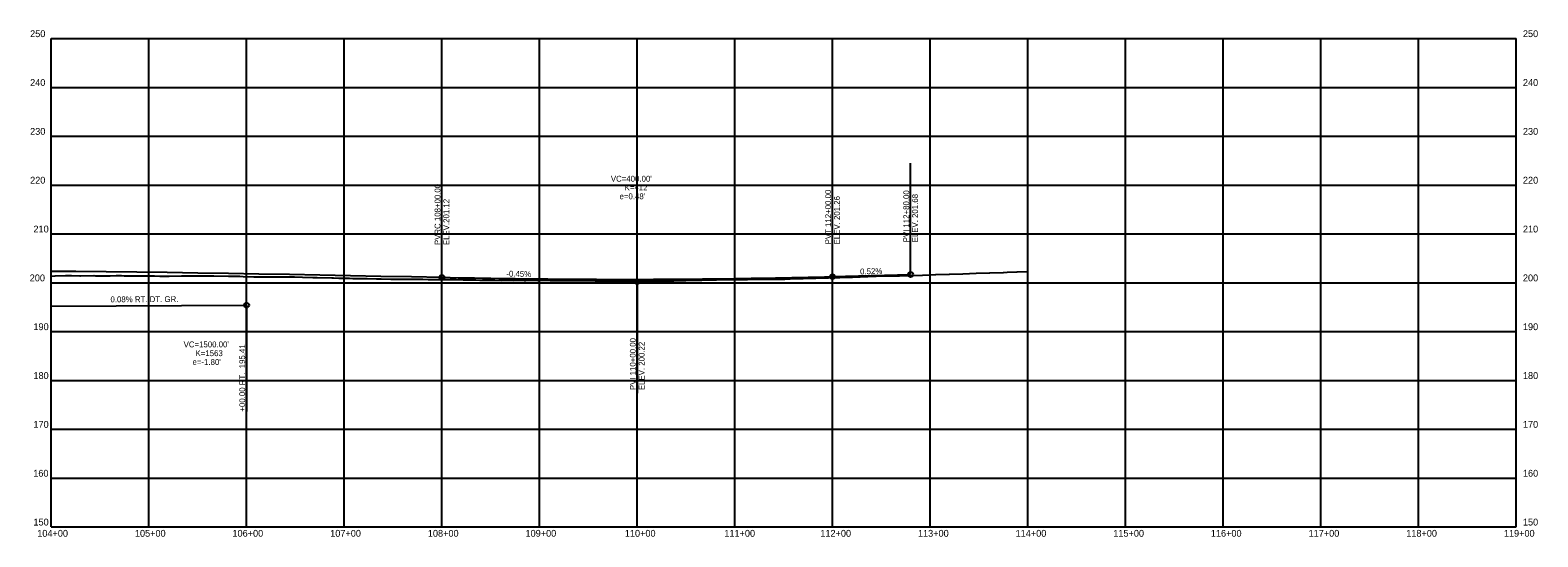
# Model space of a CAD drawing. Extents: x 1138442 to 1165793, y 1654070 to 1657687.
# Drawn here: x 1141789 to 1143333, y 1655756 to 1656275 of the extents above; entities that cross this region are included whole.
import ezdxf

# ---------------------------------------------------------------- set-up
doc = ezdxf.new("R2010")
doc.units = 0
for name, color, linetype in [('B_Dimensions', 7, 'Continuous'), ('R_Axis', 7, 'Continuous'), ('R_Axis Annot', 7, 'Continuous'), ('R_Grid', 7, 'Continuous'), ('R_Horz Alg Annot', 7, 'Continuous'), ('R_Proposed Const Limits_Hand', 7, 'Continuous'), ('R_Vert Alg Annot', 7, 'Continuous')]:
    doc.layers.add(name, color=color, linetype=linetype)

msp = doc.modelspace()

# ---------------------------------------------------------------- linework, layer by layer
at = {"layer": 'B_Dimensions'}
for p, q in [((1142610.9, 1656022.7), (1142690.9, 1656024.8)), ((1142310.9, 1656019.8), (1142410.9, 1656017.5)), ((1142410.9, 1656017.5), (1142510.9, 1656020.1)), ((1141810.9, 1655992.6), (1142010.9, 1655993.5))]:
    msp.add_line(p, q, dxfattribs=at)
for points in [[(1141810.9, 1656028.4), (1141835.9, 1656028.2), (1141867.2, 1656027.8), (1141898.4, 1656027.5), (1141929.7, 1656027.1), (1141960.9, 1656026.6), (1141992.2, 1656026.2), (1142023.4, 1656025.7), (1142054.7, 1656025.1), (1142085.9, 1656024.6), (1142117.2, 1656024), (1142148.4, 1656023.3), (1142179.7, 1656022.7), (1142210.9, 1656022)], [(1142210.9, 1656022), (1142219.3, 1656021.8), (1142227.6, 1656021.6), (1142235.9, 1656021.5), (1142244.3, 1656021.3), (1142252.6, 1656021.2), (1142260.9, 1656021), (1142269.3, 1656020.9), (1142277.6, 1656020.8), (1142285.9, 1656020.7), (1142294.3, 1656020.6), (1142302.6, 1656020.5), (1142310.9, 1656020.4), (1142319.3, 1656020.3), (1142327.6, 1656020.2), (1142335.9, 1656020.1), (1142344.3, 1656020.1), (1142352.6, 1656020), (1142360.9, 1656020), (1142369.3, 1656020), (1142377.6, 1656019.9), (1142385.9, 1656019.9), (1142394.3, 1656019.9), (1142402.6, 1656019.9), (1142419.3, 1656019.9), (1142427.6, 1656020), (1142435.9, 1656020), (1142444.3, 1656020.1), (1142452.6, 1656020.1), (1142460.9, 1656020.2), (1142469.3, 1656020.2), (1142477.6, 1656020.3), (1142485.9, 1656020.4), (1142494.3, 1656020.5), (1142502.6, 1656020.6), (1142510.9, 1656020.7), (1142519.3, 1656020.8), (1142527.6, 1656021), (1142535.9, 1656021.1), (1142544.3, 1656021.2), (1142552.6, 1656021.4), (1142560.9, 1656021.6), (1142569.3, 1656021.7), (1142577.6, 1656021.9), (1142585.9, 1656022.1), (1142594.3, 1656022.3), (1142602.6, 1656022.5), (1142610.9, 1656022.7)]]:
    msp.add_lwpolyline(points, dxfattribs=at)
msp.add_circle((1142010.9, 1655993.5), 2.5, dxfattribs=at)
at = {"layer": 'R_Axis'}
for p, q in [((1141810.9, 1655766.4), (1141810.9, 1656266.4)), ((1143310.9, 1655766.4), (1143310.9, 1656266.4)), ((1141810.9, 1655766.4), (1143310.9, 1655766.4))]:
    msp.add_line(p, q, dxfattribs=at)
at = {"layer": 'R_Grid'}
for p, q in [((1141810.9, 1656266.4), (1143310.9, 1656266.4)), ((1141810.9, 1656266.4), (1143310.9, 1656266.4)), ((1141910.9, 1655766.4), (1141910.9, 1656266.4)), ((1142010.9, 1655766.4), (1142010.9, 1656266.4)), ((1142110.9, 1655766.4), (1142110.9, 1656266.4)), ((1142210.9, 1655766.4), (1142210.9, 1656266.4)), ((1142310.9, 1655766.4), (1142310.9, 1656266.4)), ((1142410.9, 1655766.4), (1142410.9, 1656266.4)), ((1142510.9, 1655766.4), (1142510.9, 1656266.4)), ((1142610.9, 1655766.4), (1142610.9, 1656266.4)), ((1142710.9, 1655766.4), (1142710.9, 1656266.4)), ((1142810.9, 1655766.4), (1142810.9, 1656266.4)), ((1142910.9, 1655766.4), (1142910.9, 1656266.4)), ((1143010.9, 1655766.4), (1143010.9, 1656266.4)), ((1143110.9, 1655766.4), (1143110.9, 1656266.4)), ((1143210.9, 1655766.4), (1143210.9, 1656266.4)), ((1141810.9, 1656216.4), (1143310.9, 1656216.4)), ((1141810.9, 1656166.4), (1143310.9, 1656166.4)), ((1141810.9, 1656116.4), (1143310.9, 1656116.4)), ((1141810.9, 1656066.4), (1143310.9, 1656066.4)), ((1141810.9, 1656016.4), (1143310.9, 1656016.4)), ((1141810.9, 1655966.4), (1143310.9, 1655966.4)), ((1141810.9, 1655916.4), (1143310.9, 1655916.4)), ((1141810.9, 1655866.4), (1143310.9, 1655866.4)), ((1141810.9, 1655816.4), (1143310.9, 1655816.4))]:
    msp.add_line(p, q, dxfattribs=at)
at = {"layer": 'R_Proposed Const Limits_Hand'}
msp.add_lwpolyline([(1141810.9, 1656023.1), (1141814.7, 1656023.6), (1141825.3, 1656023.9), (1141825.7, 1656023.9), (1141831.5, 1656023.7), (1141840, 1656023.6), (1141840.8, 1656023.6), (1141854.4, 1656023.7), (1141856, 1656023.6), (1141861.7, 1656023.6), (1141871.1, 1656023.6), (1141877.4, 1656023.7), (1141882.7, 1656023.8), (1141885.6, 1656023.6), (1141886.3, 1656023.6), (1141899.6, 1656023.4), (1141901.4, 1656023.4), (1141906.2, 1656023.5), (1141916.6, 1656023.4), (1141922.2, 1656023.3), (1141925.6, 1656023.3), (1141931.7, 1656023.3), (1141944.1, 1656023.4), (1141946.9, 1656023.4), (1141947, 1656023.4), (1141949.6, 1656023.4), (1141962, 1656023.5), (1141969.4, 1656023.6), (1141971.3, 1656023.6), (1141977.2, 1656023.5), (1141992.3, 1656023.2), (1141994.1, 1656023.2), (1141994.9, 1656023.2), (1141995.6, 1656023.1), (1142003.8, 1656023), (1142007.5, 1656022.9), (1142018.2, 1656022.5), (1142019.2, 1656022.5), (1142022.6, 1656022.5), (1142037.7, 1656022.5), (1142038.1, 1656022.5), (1142039.5, 1656022.5), (1142052.9, 1656022.4), (1142057.8, 1656022.4), (1142059.9, 1656022.4), (1142068, 1656022.2), (1142078.6, 1656021.9), (1142082.4, 1656021.8), (1142083.2, 1656021.8), (1142098.3, 1656021.4), (1142100, 1656021.4), (1142105.2, 1656021.2), (1142113.5, 1656021.1), (1142116.4, 1656021), (1142119.7, 1656020.9), (1142128.6, 1656020.8), (1142130.6, 1656020.7), (1142134.2, 1656020.7), (1142143.8, 1656020.5), (1142144.6, 1656020.5), (1142148.6, 1656020.4), (1142158.5, 1656020.2), (1142158.9, 1656020.2), (1142163, 1656020.1), (1142172.2, 1656020.1), (1142174.1, 1656020.1), (1142177.2, 1656020), (1142186.2, 1656020), (1142189.2, 1656020), (1142191.4, 1656020), (1142196.9, 1656019.9), (1142204.4, 1656019.9), (1142205.6, 1656019.9), (1142211.4, 1656019.8), (1142219.5, 1656019.8), (1142219.8, 1656019.8), (1142225.5, 1656019.7), (1142232.7, 1656019.5), (1142234.7, 1656019.5), (1142238.7, 1656019.4), (1142245.7, 1656019.3), (1142249.8, 1656019.2), (1142251.9, 1656019.2), (1142258.7, 1656019.1), (1142265, 1656019), (1142265.2, 1656019), (1142271.6, 1656018.8), (1142278.2, 1656018.9), (1142280.1, 1656018.9), (1142284.2, 1656018.8), (1142291.1, 1656018.9), (1142295.2, 1656018.8), (1142296.7, 1656018.8), (1142304.1, 1656018.9), (1142309.2, 1656018.8), (1142310.4, 1656018.8), (1142317, 1656018.9), (1142321.8, 1656018.8), (1142325.5, 1656018.8), (1142326.4, 1656018.8), (1142334.8, 1656018.8), (1142339.2, 1656018.8), (1142340.7, 1656018.8), (1142347.8, 1656018.7), (1142351.9, 1656018.7), (1142355.8, 1656018.7), (1142360.8, 1656018.6), (1142364.6, 1656018.6), (1142371, 1656018.6), (1142373.8, 1656018.5), (1142380.2, 1656018.6), (1142386.1, 1656018.6), (1142397.5, 1656018.7), (1142401.3, 1656018.7), (1142402.9, 1656018.7), (1142416.4, 1656018.9), (1142421.1, 1656018.9), (1142423.7, 1656018.9), (1142431.6, 1656019), (1142435, 1656019), (1142446.7, 1656019), (1142446.7, 1656019), (1142448.9, 1656019), (1142460.9, 1656019.1), (1142461.9, 1656019.1), (1142462.8, 1656019.1), (1142475.1, 1656019.2), (1142476.7, 1656019.2), (1142477, 1656019.2), (1142490.9, 1656019.4), (1142492.2, 1656019.4), (1142506.9, 1656019.6), (1142507.8, 1656019.7), (1142522.9, 1656019.9), (1142523.4, 1656019.9), (1142523.8, 1656019.9), (1142538.9, 1656020.1), (1142538.9, 1656020.1), (1142539.1, 1656020.1), (1142554.7, 1656020), (1142554.8, 1656020), (1142562.2, 1656020.2), (1142567.7, 1656020.3), (1142567.7, 1656020.3), (1142580.6, 1656020.7), (1142580.8, 1656020.7), (1142593.6, 1656021), (1142593.8, 1656021), (1142606.5, 1656021.3), (1142606.9, 1656021.4), (1142630.3, 1656022.2), (1142630.9, 1656022.2), (1142631.5, 1656022.2), (1142655, 1656023), (1142655.5, 1656023), (1142679, 1656023.6), (1142679.6, 1656023.6), (1142703, 1656024.3), (1142716.4, 1656024.7), (1142716.7, 1656024.7), (1142730.2, 1656025.2), (1142730.5, 1656025.2), (1142730.7, 1656025.2), (1142744.2, 1656025.7), (1142744.4, 1656025.7), (1142757.9, 1656026.2), (1142771.8, 1656026.6), (1142771.9, 1656026.6), (1142785.9, 1656027), (1142785.9, 1656027), (1142789.6, 1656027.2), (1142799.8, 1656027.5), (1142799.9, 1656027.5), (1142810.9, 1656027.8)], dxfattribs=at)
at = {"layer": 'R_Vert Alg Annot'}
for p, q in [((1142210.9, 1656052), (1142210.9, 1656142)), ((1142610.9, 1656052.7), (1142610.9, 1656136.7)), ((1142690.9, 1656054.8), (1142690.9, 1656138.8)), ((1142610.9, 1656022.7), (1142610.9, 1656052.7)), ((1142690.9, 1656024.8), (1142690.9, 1656054.8)), ((1142210.9, 1656022), (1142210.9, 1656052)), ((1142410.9, 1656017.5), (1142410.9, 1655987.5)), ((1142010.9, 1655993.5), (1142010.9, 1655968.5)), ((1142410.9, 1655987.5), (1142410.9, 1655903.5)), ((1142010.9, 1655968.5), (1142010.9, 1655884.5))]:
    msp.add_line(p, q, dxfattribs=at)
for centre in [(1142210.9, 1656022), (1142610.9, 1656022.7), (1142690.9, 1656024.8), (1142410.9, 1656017.5)]:
    msp.add_circle(centre, 2.5, dxfattribs=at)

# ---------------------------------------------------------------- texts
at = {"layer": 'R_Axis Annot'}
for s, height, p in [('250', 7, (1141789.2, 1656267.9)), ('250', 7, (1141789.2, 1656267.9)), ('250', 7, (1143317.9, 1656267.9)), ('250', 7, (1143317.9, 1656267.9)), ('240', 7, (1141789.2, 1656217.9)), ('240', 7, (1143317.9, 1656217.9)), ('230', 7, (1141789.2, 1656167.9)), ('230', 7, (1143317.9, 1656167.9)), ('220', 7, (1141789.2, 1656117.9)), ('220', 7, (1143317.9, 1656117.9)), ('210', 7, (1141792.6, 1656067.9)), ('210', 7, (1143317.9, 1656067.9)), ('200', 7, (1141788.8, 1656017.9)), ('200', 7, (1143317.9, 1656017.9)), ('190', 7, (1141792.6, 1655967.9)), ('190', 7, (1143317.9, 1655967.9)), ('180', 7, (1141792.6, 1655917.9)), ('180', 7, (1143317.9, 1655917.9)), ('170', 7, (1141792.6, 1655867.9)), ('170', 7, (1143317.9, 1655867.9)), ('160', 7, (1141792.4, 1655817.9)), ('160', 7, (1143317.9, 1655817.9)), ('150', 7, (1141792.6, 1655767.9)), ('150', 7, (1143317.9, 1655767.9)), ('104+00', 7, (1141796.5, 1655756.4)), ('-', 0.0001, (1141810.9, 1655766.4)), ('105+00', 7, (1141896.5, 1655756.4)), ('106+00', 7, (1141996.4, 1655756.4)), ('107+00', 7, (1142096.5, 1655756.4)), ('108+00', 7, (1142196.5, 1655756.4)), ('109+00', 7, (1142296.5, 1655756.4)), ('110+00', 7, (1142398.2, 1655756.4)), ('111+00', 7, (1142500.1, 1655756.4)), ('112+00', 7, (1142598.4, 1655756.4)), ('113+00', 7, (1142698.4, 1655756.4)), ('114+00', 7, (1142798.4, 1655756.4)), ('115+00', 7, (1142898.4, 1655756.4)), ('116+00', 7, (1142998.3, 1655756.4)), ('117+00', 7, (1143098.4, 1655756.4)), ('118+00', 7, (1143198.4, 1655756.4)), ('119+00', 7, (1143298.4, 1655756.4))]:
    msp.add_text(s, height=height, dxfattribs=at).set_placement(p)
at = {"layer": 'R_Horz Alg Annot'}
msp.add_text('-0.45%', height=6, rotation=358.698, dxfattribs=at).set_placement((1142276.8, 1656022.8))
at = {"layer": 'R_Vert Alg Annot'}
for s, rotation, p in [('PVRC 108+00.00', 90, (1142209.4, 1656055)), ('ELEV.201.12', 90, (1142218.4, 1656055)), ('PVT 112+00.00', 90, (1142609.4, 1656055.7)), ('ELEV. 201.26', 90, (1142618.4, 1656055.7)), ('PVI 112+80.00', 90, (1142689.4, 1656057.8)), ('ELEV. 201.68', 90, (1142698.4, 1656057.8)), ('0.52%', 1.4894, (1142639.2, 1656024.9)), ('0.08% RT. DT. GR.', 0.2349, (1141871.5, 1655996.4)), ('+00.00 RT.  195.41', 90, (1142009.4, 1655884.5)), ('PVI 110+00.00', 90, (1142409.4, 1655906.5)), ('ELEV. 200.22', 90, (1142418.4, 1655906.5))]:
    msp.add_text(s, height=6, rotation=rotation, dxfattribs=at).set_placement(p)
for s, p in [("VC=400.00'", (1142383.9, 1656119.9)), ('K=412', (1142398, 1656110.9)), ("e=0.48'", (1142392.8, 1656101.9)), ("VC=1500.00'", (1141946.4, 1655950.3)), ('K=1563', (1141958.6, 1655941.3)), ("e=-1.80'", (1141955.5, 1655932.3))]:
    msp.add_text(s, height=6, dxfattribs=at).set_placement(p)

doc.saveas('drawing.dxf')
